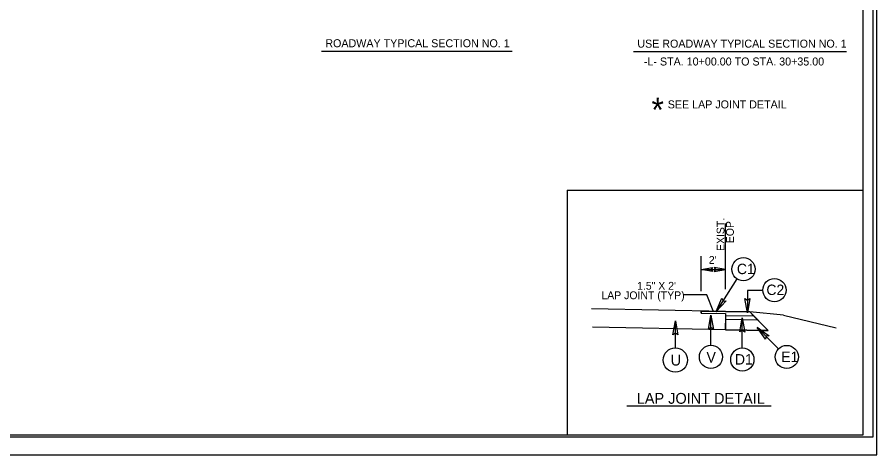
# Model space of a CAD drawing. Extents: x 2111095 to 2115970, y 670428 to 672393.
# Drawn here: x 2112193 to 2113268, y 671116 to 671663 of the extents above; entities that cross this region are included whole.
import ezdxf

# ---------------------------------------------------------------- set-up
doc = ezdxf.new("R2010")
doc.units = 0
for name, color, linetype in [('Exist XS Ground Line', 7, 'Continuous'), ('Old_Level_11', 7, 'Continuous'), ('Old_Level_19', 7, 'Continuous'), ('Old_Level_20', 7, 'Continuous'), ('Old_Level_3', 7, 'Continuous'), ('Prop Shade Light', 7, 'Continuous'), ('Prop Shade Medium', 7, 'Continuous'), ('Sheet Cutting Line CELL', 7, 'Continuous'), ('Sheet Plot Border Inside CELL', 7, 'Continuous'), ('Sheet Plot Border Outside CELL', 7, 'Continuous'), ('Sheet Typical CELL', 7, 'Continuous'), ('Typical ID Circle CELL', 7, 'Continuous'), ('Typical Pavement Slope CELL', 7, 'Continuous'), ('Typical Pavement Slope Information CELL', 7, 'Continuous'), ('Typical Terminator CELL', 7, 'Continuous'), ('Typical Text Grade Point CELL', 7, 'Continuous'), ('Typical Text ID Circle CELL', 7, 'Continuous')]:
    doc.layers.add(name, color=color, linetype=linetype)

msp = doc.modelspace()

# ---------------------------------------------------------------- linework, layer by layer
at = {"layer": 'Exist XS Ground Line'}
for p, q in [((2113078.4, 671295.1), (2112911.2, 671298.4)), ((2113078.4, 671272.4), (2112912.3, 671275.7))]:
    msp.add_line(p, q, dxfattribs=at)
at = {"layer": 'Old_Level_11'}
msp.add_line((2113015.8, 671249.6), (2113015.9, 671283.5), dxfattribs=at)
msp.add_lwpolyline([(2113012.8, 671266), (2113015.9, 671283.5), (2113019, 671265.9), (2113015.8, 671268.1)], close=True, dxfattribs=at)
msp.add_circle((2113015.8, 671234.4), 15.2, dxfattribs=at)
at = {"layer": 'Old_Level_19'}
for q in [(2112880.5, 671141), (2113250.5, 671446.9)]:
    msp.add_line((2112880.5, 671446.9), q, dxfattribs=at)
at = {"layer": 'Old_Level_3'}
for p, q in [((2112573.8, 671620.3), (2112812.1, 671620.3)), ((2112963.6, 671619.8), (2113229.5, 671619.8)), ((2112955.3, 671177.2), (2113135.7, 671177.2))]:
    msp.add_line(p, q, dxfattribs=at)
at = {"layer": 'Prop Shade Light'}
for p, q in [((2113060.2, 671287.2), (2113060.3, 671287)), ((2113060.2, 671287), (2113060.2, 671287.2)), ((2113123.6, 671279.6), (2113116.9, 671286.3)), ((2113078.4, 671280.5), (2113078.4, 671272.4)), ((2113078.4, 671272.4), (2113131.8, 671271.3)), ((2113078.4, 671272.4), (2113120.6, 671271.6)), ((2113131.8, 671271.3), (2113123.6, 671279.6)), ((2113131.8, 671271.3), (2113123.6, 671279.6)), ((2113123.3, 671271.5), (2113131.8, 671271.3))]:
    msp.add_line(p, q, dxfattribs=at)
at = {"layer": 'Prop Shade Medium'}
for p, q in [((2113067.1, 671295.3), (2113048.2, 671295.7)), ((2113048.2, 671295.7), (2113048.2, 671293.1)), ((2113048.2, 671293.1), (2113078.4, 671292.7)), ((2113078.4, 671295.1), (2113067.2, 671295.3)), ((2113105.7, 671294.5), (2113078.4, 671295.1)), ((2113108.7, 671294.5), (2113106, 671294.5)), ((2113113.5, 671289.6), (2113108.7, 671294.5)), ((2113078.4, 671292.7), (2113078.4, 671290.3)), ((2113078.4, 671290.3), (2113113.5, 671289.6))]:
    msp.add_line(p, q, dxfattribs=at)
for points in [[(2113067.2, 671295.3), (2113066.9, 671295), (2113067.1, 671295.3)], [(2113106, 671294.5), (2113105.9, 671293.5), (2113105.7, 671294.5)], [(2113078.4, 671290.3), (2113078.4, 671290.3)]]:
    msp.add_lwpolyline(points, dxfattribs=at)
at = {"layer": 'Sheet Cutting Line CELL'}
msp.add_line((2111583.5, 671116), (2113267.5, 671116), dxfattribs=at)
at = {"layer": 'Sheet Plot Border Inside CELL'}
msp.add_lwpolyline([(2113263, 672193.6), (2111596.5, 672193.6), (2111596.5, 671138.5), (2113263, 671138.5)], close=True, dxfattribs=at)
at = {"layer": 'Sheet Plot Border Outside CELL'}
msp.add_lwpolyline([(2113267.5, 672216), (2111583.5, 672216), (2111583.5, 671116), (2113267.5, 671116)], close=True, dxfattribs=at)
at = {"layer": 'Sheet Typical CELL'}
msp.add_lwpolyline([(2113250.5, 672191), (2111750.5, 672191), (2111750.5, 671141), (2113250.5, 671141)], close=True, dxfattribs=at)
at = {"layer": 'Typical ID Circle CELL'}
for p, q in [((2113092.8, 671335.9), (2113066.9, 671295)), ((2113060.3, 671252.9), (2113060.3, 671290.5)), ((2113099.5, 671249.6), (2113099.5, 671287.2)), ((2113144.7, 671248.6), (2113118.1, 671275.2))]:
    msp.add_line(p, q, dxfattribs=at)
msp.add_lwpolyline([(2113125.1, 671321.4), (2113105.9, 671321.4), (2113105.9, 671293.5)], dxfattribs=at)
for centre in [(2113100.9, 671347.9), (2113139.6, 671321.8), (2113060.3, 671238.4), (2113155, 671238.3), (2113099.5, 671235.1)]:
    msp.add_circle(centre, 14.5, dxfattribs=at)
at = {"layer": 'Typical Pavement Slope CELL'}
for p, q in [((2113078.4, 671323.2), (2113078.4, 671405.1)), ((2113048.2, 671320.7), (2113048.2, 671364.2)), ((2113048.2, 671347.6), (2113078.4, 671347.6)), ((2113048.2, 671293.1), (2113048.2, 671295.7)), ((2113048.2, 671295.7), (2113078.4, 671295.1)), ((2113048.2, 671293.1), (2113078.5, 671292.7)), ((2113108.7, 671294.5), (2113078.4, 671295.1)), ((2113078.4, 671295.1), (2113108.7, 671294.5)), ((2113151.1, 671290.6), (2113108.7, 671294.5)), ((2113108.7, 671294.5), (2113118.5, 671284.6)), ((2113108.7, 671294.5), (2113131.8, 671271.3)), ((2113078.4, 671292.7), (2113078.4, 671272.4)), ((2113078.4, 671290.3), (2113113.5, 671289.6)), ((2113078.4, 671287), (2113078.4, 671272.4)), ((2113078.4, 671285.4), (2113118.5, 671284.6)), ((2113078.4, 671285.4), (2113118.5, 671284.6)), ((2113151.1, 671290.6), (2113216.8, 671274.5)), ((2113078.4, 671272.4), (2113078.4, 671280.5)), ((2113131.8, 671271.3), (2113078.4, 671272.4)), ((2113131.8, 671271.3), (2113078.4, 671272.4)), ((2113123.6, 671279.6), (2113131.8, 671271.3))]:
    msp.add_line(p, q, dxfattribs=at)
msp.add_lwpolyline([(2113062.9, 671295.8), (2113055.1, 671316), (2113026.5, 671316)], dxfattribs=at)
at = {"layer": 'Typical Terminator CELL'}
for points in [[(2113062.4, 671345.2), (2113048.2, 671347.6), (2113062.4, 671350.1), (2113060.6, 671347.6)], [(2113064.3, 671345.2), (2113078.4, 671347.6), (2113064.2, 671350.1), (2113066, 671347.6)], [(2113079.1, 671308.3), (2113066.9, 671295), (2113073.9, 671311.7), (2113075.4, 671308.1)], [(2113108.9, 671311.2), (2113105.9, 671293.5), (2113102.7, 671311.3), (2113105.9, 671309.1)], [(2113057.2, 671272.8), (2113060.3, 671290.5), (2113063.4, 671272.7), (2113060.3, 671275)], [(2113061.5, 671283.4), (2113060.3, 671290.5), (2113059, 671283.4), (2113060.3, 671284.3)], [(2113096.5, 671269.5), (2113099.5, 671287.2), (2113102.7, 671269.4), (2113099.5, 671271.6)], [(2113100.7, 671280.1), (2113099.5, 671287.2), (2113098.3, 671280.1), (2113099.5, 671281)], [(2113124, 671271), (2113118.1, 671275.2), (2113122.3, 671269.2), (2113122.5, 671270.8)], [(2113128.5, 671260.5), (2113118.1, 671275.2), (2113132.9, 671264.8), (2113129.1, 671264.2)]]:
    msp.add_lwpolyline(points, close=True, dxfattribs=at)

# ---------------------------------------------------------------- texts
at = {"layer": 'Old_Level_20'}
msp.add_text('U', height=13.6, rotation=359.9032, dxfattribs=at).set_placement((2113009.9, 671227.6))
at = {"layer": 'Typical Pavement Slope Information CELL'}
for s, height, rotation, p in [('*', 29.9, 358.8561, (2112985.5, 671532.4)), ('EXIST.', 9.79, 90.0019, (2113077.2, 671370.7)), ('EOP', 9.79, 90.0019, (2113088.9, 671380.5)), ("2'", 9.79, 358.8561, (2113057.5, 671354.7)), ('1.5" X 2\'', 9.79, 0.0019, (2112968, 671322.3)), ('LAP JOINT (TYP)', 9.792, 0.0019, (2112923.4, 671310.5))]:
    msp.add_text(s, height=height, rotation=rotation, dxfattribs=at).set_placement(p)
at = {"layer": 'Typical Text Grade Point CELL'}
for s, height, rotation, p in [('ROADWAY TYPICAL SECTION NO. 1', 10, 360, (2112578.5, 671625.3)), ('USE ROADWAY TYPICAL SECTION NO. 1', 10, 360, (2112968.3, 671624.8)), ('-L- STA. 10+00.00 TO STA. 30+35.00', 10, 360, (2112976.5, 671602.5)), ('SEE LAP JOINT DETAIL', 10, 360, (2113006.3, 671548.9)), ('LAP JOINT DETAIL', 13.537, 359.9981, (2112967.6, 671179.8))]:
    msp.add_text(s, height=height, rotation=rotation, dxfattribs=at).set_placement(p)
at = {"layer": 'Typical Text ID Circle CELL'}
for s, height, p in [('C1', 13.02, (2113092.7, 671341.8)), ('C2', 13.02, (2113129.6, 671315.7)), ('V', 13, (2113054.8, 671231.3)), ('D1', 13.02, (2113090.3, 671228.8)), ('E1 ', 13.02, (2113148.1, 671231.9))]:
    msp.add_text(s, height=height, rotation=0.0019, dxfattribs=at).set_placement(p)

doc.saveas('drawing.dxf')
